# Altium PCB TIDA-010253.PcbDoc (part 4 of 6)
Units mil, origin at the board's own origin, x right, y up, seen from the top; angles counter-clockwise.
Board outline 5525 x 6695 mil, 4 copper layers (Top Layer, Signal Layer 1, Signal Layer 2, Bottom Layer), stack 61.2 mil thick; 522 components, 391 nets, 1722 pads, 1048 vias.
Unrouted connection lines stored in the file: 22.
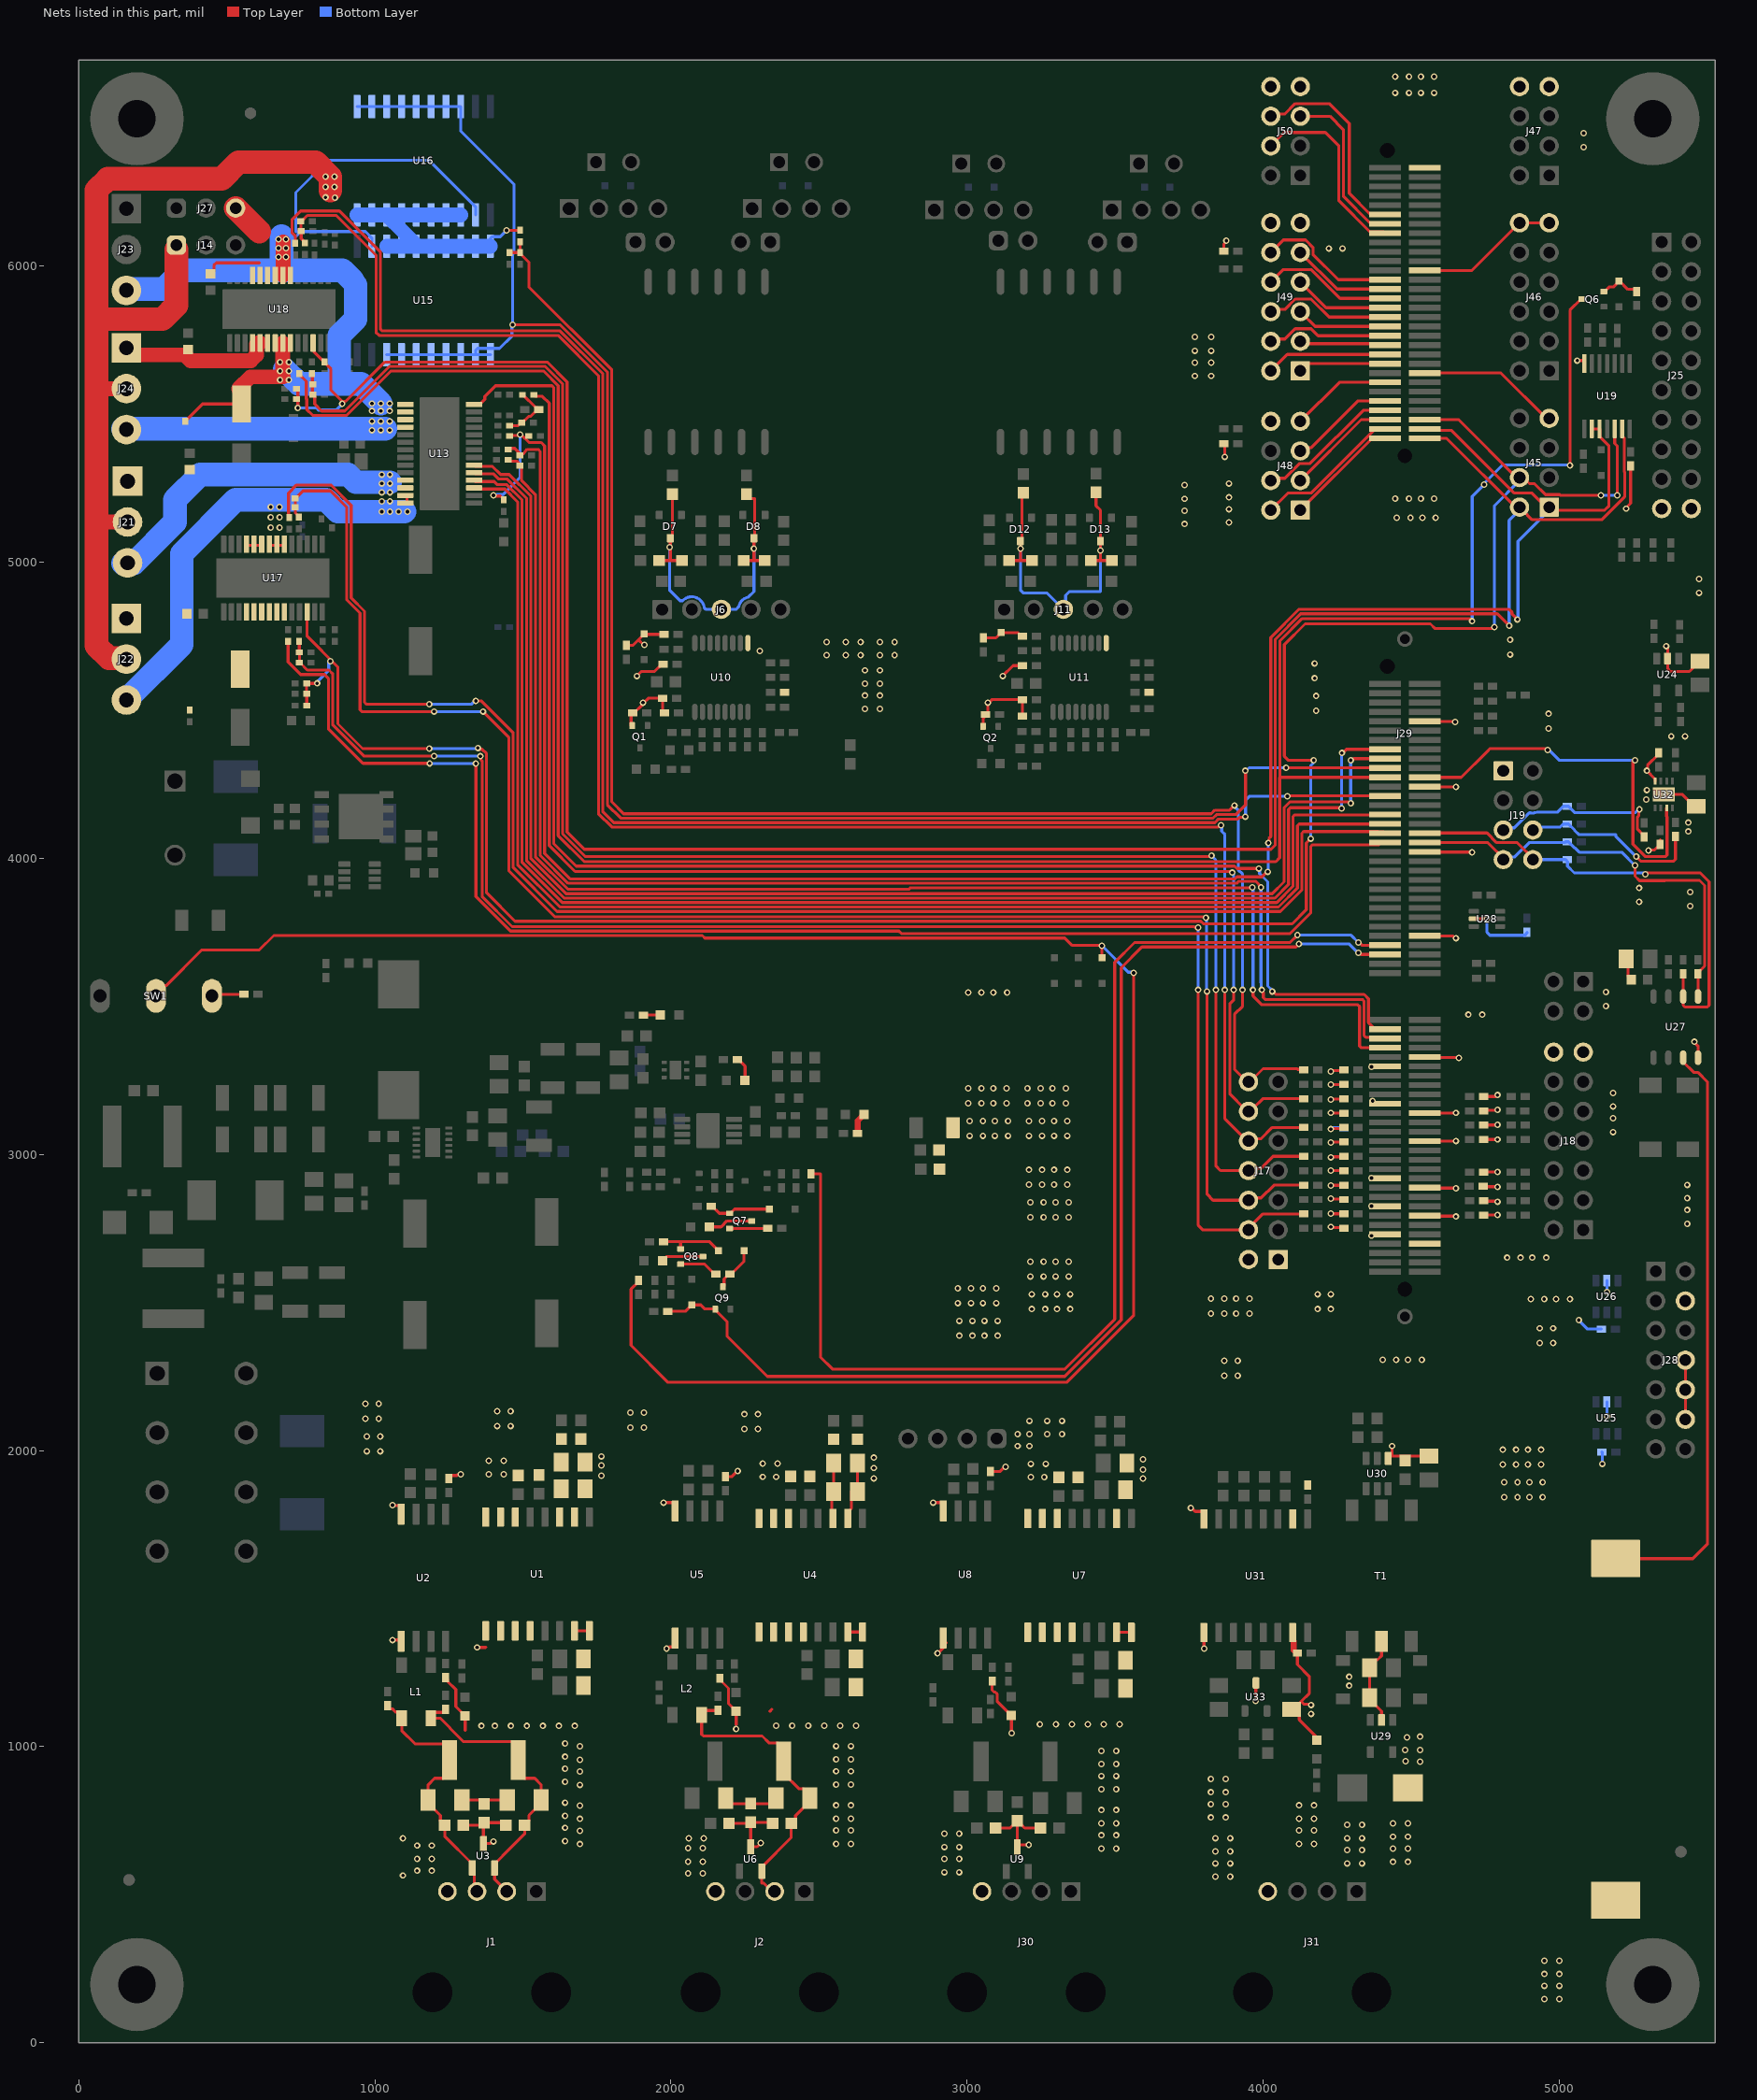
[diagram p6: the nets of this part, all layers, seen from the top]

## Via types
v1: diameter 22, hole 12, Top Layer to Bottom Layer, 944 vias
v2: diameter 19.68, hole 7.87, Top Layer to Bottom Layer, 76 vias
v3: diameter 19.68, hole 7.87, Top Layer to Bottom Layer, tented both sides, 16 vias
v4: diameter 22, hole 12, Top Layer to Bottom Layer, tented both sides, 12 vias

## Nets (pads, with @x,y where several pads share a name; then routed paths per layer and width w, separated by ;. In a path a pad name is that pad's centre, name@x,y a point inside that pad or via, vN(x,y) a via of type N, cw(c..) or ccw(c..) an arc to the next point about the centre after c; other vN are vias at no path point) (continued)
GND: BT1.1 C1.1 C3.2 C8.1 C10.2 C15.1 C17.2 C19.2 C20.2 C21.1 C22.2 C23.2 C24.1 C25.2 C26.2 C27.1 C28.1 C29.2 C30.2 C31.2 C32.1 C33.2 C34.2 C35.1 C36.2 C37.2 C38.1 C39.1 C40.2 C75.2 C107.2 C108.2 C109.2 C110.2 C111.2 C112.2 C113.2 C117.2 C118.2 C119.2 C120.2 C121.2 C122.2 C123.2 C124.2 C125.2 C128.2 C129.2 C131.2 C132.2 C133.2 C134.2 C138.1 C141.2 C142.1 C143.2 C144.2 C145.2 C146.2 C147.2 CO1.2 CO3.2 CO5.2 D7.3 D8.3 D9.2 D12.3 D13.3 D14.2 D23.2 F2.2 J6.3 J11.3 J17.1 J17.2 J18.13 J18.14 J19.1 J25.19 J25.20 J28.4 J28.8 J28.10 J28.12 J29.7 J29.10 J29.13 J29.16 J29.19 J29.22 J29.29 J29.35 J29.38 J29.46 J29.47 J29.65 J29.83 J29.97 J29.111 J29.135 J29.157 J29.179 J45.7 J46.11 J46.12 J47.7 J47.8 J48.8 J49.11 J49.12 J50.7 J50.8 L3.2 L7.2 Q1.2 Q2.2 Q6.2 R6.1 R9.1 R19.1 R21.1 R32.1 R34.1 R46.1 R50.2 R63.1 R67.2 R120.1 R161.1 R201.2 R202.2 R219.2 R220.2 U1.2 U1.6 U1.7 U1.8 U2.4 U4.2 U4.6 U4.7 U4.8 U5.4 U7.2 U7.6 U7.7 U7.8 U8.4 U10.9 U11.9 U19.7 U24.2 U25.2 U26.2 U27.4 U28.2 U30.4 U31.2 U31.8 U32.8 U32.9 | length 9247.4
  Top Layer w10: v1(1060,1815) 1060.71,1814.29 1082.36,1814.29 1089.17,1807.48 U2.4@1089.17,1785.16 ; C1.1@1249.17,1904.65 1249.17,1908.58 1255.98,1915.39 1277.15,1915.39 1281.75,1920 v1@1285,1920 ; C29.2@1850,4718.62 1872.01,4718.62 1889.61,4736.23 ; Q1.2@1864.41,4447.4 1865,4447.99 R50.2@1865,4490 ; R50.2@1871.38,4490 1875.32,4490 1902.7,4517.39 1902.7,4522.7 v1(1905,4525) 1908.25,4525 1923.25,4540 C25.2@1971.38,4540 C23.2@1971.38,4490 ; v1(1885,4615) 1900,4630 1943.82,4630 1968.82,4655 C19.2@1972.76,4655 C19.2@1969.45,4651.69 ; v1(1910,4720) 1906.75,4720 1890.53,4736.23 1889.61,4736.23 ; C20.2@1960,5005 1998.5,5005 ; v1(1975,1824) 2007.36,1824 2014.17,1817.19 U5.4@2014.17,1796.02 ; C22.2@1976.38,4755 1975.53,4755.85 1975.49,4755.81 1910.81,4755.81 D9.2@1910,4756.61 1889.61,4736.23 ; C21.1@2005,5228.5 2005,5089.62 1997.4,5082.03 D7.3@1997.4,5080.06 1997.4,5006.1 1998.5,5005 ; C24.1@2037.01,5005 1998.5,5005 ; C8.1@2184.17,1912.03 2206.17,1912.03 v1(2225,1930.87) ; C28.1@2245,5005 2281,5005 ; C27.1@2255,5228.5 2255,5227.52 2268.7,5213.82 2281.59,5213.82 2282.7,5212.7 2282.7,5082.76 D8.3@2280,5080.06 D8.3@2280,5079.11 ; D8.3@2286.81,5072.3 D8.3@2280,5079.11 ; C26.2@2317.01,5005 2281,5005 ; U4.2@2596.67,1770.75 2596.67,1791.42 2609.17,1803.92 CO3.2@2609.17,1861.89 ; CO3.2@2629.17,1861.89 C10.2@2629.17,1956.89 ; v1(2885,1824) 2912.36,1824 2912.36,1824.29 2919.17,1817.48 U8.4@2919.17,1796.02 ; Q2.2@3054.41,4437.4 3054.41,4473.19 3061.22,4480 R67.2@3061.38,4480 ; C40.2@3055,4747.56 C40.2@3055,4743.62 3097.01,4743.62 D14.2@3115,4761.61 3170.83,4761.61 3182.44,4750 C33.2@3186.38,4750 ; R67.2@3061.38,4485 3063.19,4485 3070,4491.81 v1@3070,4520 ; v1@3075.54,4522.7 3072.7,4522.7 v1@3070,4520 ; C15.1@3079.17,1928.62 3110.37,1928.62 3126.75,1945 v1(3130,1945) ; v1(3120,4615) 3155,4650 C30.2@3186.38,4650 ; C31.2@3141.5,5004.93 3180,5004.93 ; C32.1@3183.57,5240 C32.1@3190.07,5233.5 3185,5228.44 3185,5075.63 D12.3@3180,5070.63 v4(3180,5045) 3180,5004.93 ; C34.2@3186.38,4480 C36.2@3186.38,4535 3083.25,4535 3073.25,4525 v1(3070,4525) v1@3070,4520 ; C35.1@3218.5,5004.93 3180,5004.93 ; C39.1@3417.99,5005 3453.25,5005 ; C38.1@3425.07,5245 C38.1@3435.07,5235 3435.07,5189.93 3450,5175 D13.3@3450,5070.63 D13.3@3450,5069.11 ; D13.3@3456.81,5062.3 D13.3@3450,5069.11 ; C37.2@3488.5,5005 3453.25,5005 ; v1(3755,1805.87) 3758.25,1805.87 3769.82,1794.29 3792.36,1794.29 3799.17,1787.48 U31.8@3799.17,1768.82 ; R202.2@3866.38,5400 3870,5396.38 v4(3870,5355) ; R201.2@3866.38,6050 3866.38,6073.6 3875,6082.22 v4(3875,6085) ; J48.8@4025,5475 J48.8@4032.56,5482.56 ; v1@4230,2755 4232.3,2752.7 4268.67,2752.7 C109.2@4271.38,2750 ; v1@4230,2800 4230.68,2799.32 4270.7,2799.32 C110.2@4271.38,2798.64 ; v1@4230,2850 4231.36,2848.64 4270.01,2848.64 C118.2@4271.38,2847.27 ; v1@4230,2895 4230.45,2895.45 4270.92,2895.45 C119.2@4271.38,2895.91 ; v1@4230,2945 4230.23,2944.77 4271.15,2944.77 C122.2@4271.38,2944.55 ; v1@4230,2990 4231.59,2991.59 4269.79,2991.59 C123.2@4271.38,2993.18 ; v1@4230,3040 4230.91,3040.91 4270.47,3040.91 C124.2@4271.38,3041.82 ; v1@4230,3140 4230.45,3139.55 4272.3,3139.55 C133.2@4272.76,3139.09 ; v1@4230,3185 4231.36,3186.36 4270.01,3186.36 C134.2@4271.38,3187.73 ; v1@4230,3235 4230.68,3235.68 4270.7,3235.68 C146.2@4271.38,3236.36 ; v1@4230,3280 4232.3,3282.3 4268.67,3282.3 C147.2@4271.38,3285 ; v1@4232.3,3087.3 4268.22,3087.3 C125.2@4271.38,3090.45 ; J29.46@4360,3295 4360.83,3295.83 4410.31,3295.83 J29.46@4411.14,3296.65 ; v1(4365,2725) 4367.3,2727.3 4408.71,2727.3 J29.10@4411.14,2729.72 ; v1(4365,2825) 4365.39,2824.61 4410.75,2824.61 J29.16@4411.14,2824.21 ; J29.22@4370,2920 4370.65,2919.35 4410.49,2919.35 J29.22@4411.14,2918.7 ; J29.38@4370,3180 4373.25,3180 4377.74,3175.51 4406.3,3175.51 J29.38@4411.14,3170.67 ; v1(4435,2015) 4435,1980.87 C141.2@4559.17,1980.87 ; J29.13@4545,2792.72 4546.36,2791.36 4648.64,2791.36 v1(4650,2790) ; J29.19@4545,2887.2 4546.1,2886.1 4648.9,2886.1 v1(4650,2885) ; J29.29@4545,3044.69 4545.16,3044.84 4649.84,3044.84 v1(4650,3045) ; J29.35@4545,3139.17 4545.41,3139.59 4649.59,3139.59 v1(4650,3140) ; J29.47@4545,3328.15 4546.57,3326.57 4658.43,3326.57 v1(4660,3325) ; J29.65@4545,3737.6 4639.15,3737.6 4646.75,3730 v1(4650,3730) ; J29.83@4545,4021.06 4545.53,4020.53 4704.47,4020.53 v1(4705,4020) ; J29.97@4545,4241.54 4545.77,4240.77 4649.23,4240.77 v1(4650,4240) ; J29.111@4545,4462.01 4546,4461 4644,4461 v1@4645,4460 ; J29.135@4545,5637.91 4802.09,5637.91 J45.7@4957.44,5482.56 ; J29.157@4545,5984.37 4704.37,5984.37 J46.12@4865,6145 J46.11@4965,6145 ; U28.2@4710.71,3795 v1(4755,3795) ; C120.2@4742.24,2891.67 4743.08,2890.83 4792.67,2890.83 v1@4793.5,2890 ; C111.2@4743.62,2795 v1@4793.5,2795 ; C112.2@4743.62,2843.33 4745.29,2841.67 4791.83,2841.67 v1@4793.5,2840 ; C121.2@4743.62,2940 v1@4793.5,2940 ; C131.2@4743.62,3050 v1@4793.5,3050 ; C132.2@4743.62,3098.33 4744.46,3099.17 4792.67,3099.17 v1@4793.5,3100 ; C144.2@4743.62,3146.67 4745.29,3148.33 4791.83,3148.33 v1@4793.5,3150 ; C145.2@4743.62,3195 4785.25,3195 4790.25,3200 v1@4793.5,3200 ; v1(5060,5680) 5081.93,5680 5083.82,5678.11 U19.7@5083.82,5670 ; Q6.2@5149.9,5913.09 5152.46,5913.09 5167.53,5928.16 5181.55,5928.16 5202.5,5949.11 5231.12,5920.49 5250.69,5920.49 5257.5,5913.68 R120.1@5257.5,5909.74 ; C143.2@5212.5,3659.49 5231.63,3640.36 5231.63,3600.24 C108.2@5242.38,3589.49 ; v1(5225,5180) 5225,5183.25 5240,5198.25 C75.2@5240,5325 ; v1(5300,4026) 5301.3,4027.3 5320.92,4027.3 5329.25,4035.63 5333.19,4035.63 R219.2@5339.31,4041.75 ; U32.8@5322.32,4260 5322.32,4266.73 5321.38,4267.68 5321.38,4268.62 v1(5295,4295) 5297.3,4297.3 5297.3,4313.36 5335,4351.06 R220.2@5335,4355 ; U32.9@5338.07,4214.72 U32.9@5351.85,4214.72 5415.15,4214.72 5454.88,4175 C142.1@5461.38,4175 ; R219.2@5340,4046.38 5340,4042.44 R219.2@5339.31,4041.75 ; R219.2@5340,4061.38 5339.31,4060.69 R219.2@5339.31,4041.75 ; v1@5353.98,4715.87 5353.98,4715.49 v1@5356.79,4712.68 ; v1(5360,4715.87) 5359.98,4712.62 5365,4707.6 U24.2@5365,4674.13 5365,4640 5375,4630 5438.5,4630 5473.5,4665 C107.2@5490,4665 ; J28.12@5425,2105 J28.10@5425,2205 J28.8@5425,2305 ; v1(5455,3380) 5455,3378.25 5467.5,3365.75 U27.4@5467.5,3326.14 U27.4@5467.5,3314.93 ; D8.3@2280,5079.11 v4(2280,5045) 2280,5006 2281,5005 ; D13.3@3450,5069.11 v4(3450,5038.68) 3450,5008.25 3453.25,5005
  Bottom Layer w10: v4(1995,5050) 1995,4905 2030.88,4869.12 2035.02,4869.12 2039.07,4869.12 cw(c2070,4840) 2111.71,4848.04 ccw(c2121.52,4850) 2115.74,4841.84 2118.34,4840 2121.52,4840 J6.3@2170,4840 2220,4840 2228.35,4848.35 cw(c2270,4840) 2261.65,4881.65 2280,4900 v4(2280,5045) ; v4(3180,5045) 3180,4905 3190,4895 3270,4895 J11.3@3325,4840 3332.48,4847.48 3332.48,4887.48 3345,4900 3450,4900 v4(3450,5038.68) ; v1(4227.5,3085) 4230.75,3085 4235.75,3090 R161.1@4271.38,3090 ; v1(4755,3795) 4755,3749.36 4765.11,3739.25 4883.19,3739.25 4883.19,3740 4890,3746.81 C117.2@4890,3750 ; v1(5065,2440) 5095,2410 C129.2@5141.38,2410 ; C128.2@5142.76,1995 5145,1992.76 v1(5145,1955) ; v1(5160,2115) U25.2@5160,2164.13 ; v1(5160,2535) U26.2@5160,2574.13
  other v1: 4949.31,147.36 4999.31,147.36 4949.31,192.36 4999.31,192.36 4949.31,232.36 4999.31,232.36 4949.31,277.36 4999.31,277.36 4813.14,1842.59 4858.14,1842.59 4898.14,1842.59 4943.14,1842.59 4813.14,1892.59 4858.14,1892.59 4898.14,1892.59 4943.14,1892.59 3594,1905 2685,1905.87 3215,1910 3260,1910 2310,1910.87 2355,1910.87 1765,1915 1290,1920 1385,1920 1435,1920 3594,1935 2685,1940.87 1765,1950 4808.14,1952.59 4853.14,1952.59 4893.14,1952.59 4938.14,1952.59 3215,1955 3265,1955 2310,1955.87 2360,1955.87 1385,1965 1435,1965 3594,1970 2685,1975.87 1765,1980 973.14,1997.59 1018.14,1997.59 4808.14,2002.59 4853.14,2002.59 4893.14,2002.59 4938.14,2002.59 3170,2015 3210,2015 973.14,2047.59 1018.14,2047.59 3170,2055 3210,2055 3270,2055 3320,2055 2248.14,2072.59 2293.14,2072.59 1863.14,2077.59 1908.14,2077.59 1413.14,2082.59 1458.14,2082.59 3210,2100 3270,2100 3320,2100 968.14,2107.59 1013.14,2107.59 2248.14,2122.59 2293.14,2122.59 1863.14,2127.59 1908.14,2127.59 1413.14,2132.59 1458.14,2132.59 968.14,2157.59 1013.14,2157.59 3868.14,2252.59 3913.14,2252.59 3868.14,2302.59 3913.14,2302.59 4403.14,2306 4448.14,2306 4488.14,2306 4535,2306 4933.14,2362.59 4978.14,2362.59 2973.14,2387.59 3018.14,2387.59 3058.14,2387.59 3103.14,2387.59 4933.14,2412.59 4978.14,2412.59 2973.14,2437.59 3018.14,2437.59 3058.14,2437.59 3103.14,2437.59 3823.14,2462.59 3868.14,2462.59 3908.14,2462.59 3953.14,2462.59 3218.14,2477.59 3263.14,2477.59 3303.14,2477.59 3348.14,2477.59 4183.14,2477.59 4228.14,2477.59 2968.14,2497.59 3013.14,2497.59 3053.14,2497.59 3098.14,2497.59 4903.14,2511 4948.14,2511 4988.14,2511 5035,2511 3823.14,2512.59 3868.14,2512.59 3908.14,2512.59 3953.14,2512.59 3218.14,2527.59 3263.14,2527.59 3303.14,2527.59 3348.14,2527.59 4183.14,2527.59 4228.14,2527.59 2968.14,2547.59 3013.14,2547.59 3053.14,2547.59 3098.14,2547.59 3213.14,2587.59 3258.14,2587.59 3298.14,2587.59 3343.14,2587.59 3213.14,2637.59 3258.14,2637.59 3298.14,2637.59 3343.14,2637.59 4823.14,2651 4868.14,2651 4908.14,2651 4955,2651 4227.5,2755 5431,2765 3213.14,2787.59 3258.14,2787.59 3298.14,2787.59 3343.14,2787.59 4790.5,2795 4227.5,2800 5431,2811.86 3213.14,2837.59 3258.14,2837.59 3298.14,2837.59 3343.14,2837.59 4790.5,2840 4227.5,2850 5431,2851.86 4790.5,2890 4227.5,2895 5431,2896.86 3208.14,2897.59 3253.14,2897.59 3293.14,2897.59 3338.14,2897.59 4365,2920 4790.5,2940 4227.5,2945 3208.14,2947.59 3253.14,2947.59 3293.14,2947.59 3338.14,2947.59 4227.5,2990 4227.5,3040 4790.5,3050 3008.14,3062.59 3053.14,3062.59 3093.14,3062.59 3138.14,3062.59 3208.14,3062.59 3253.14,3062.59 3293.14,3062.59 3338.14,3062.59 5181,3075 4790.5,3100 3008.14,3112.59 3053.14,3112.59 3093.14,3112.59 3138.14,3112.59 3208.14,3112.59 3253.14,3112.59 3293.14,3112.59 3338.14,3112.59 5181,3121.86 4227.5,3140 4790.5,3150 5181,3161.86 3003.14,3172.59 3048.14,3172.59 3088.14,3172.59 3133.14,3172.59 3203.14,3172.59 3248.14,3172.59 3288.14,3172.59 3333.14,3172.59 4369,3180 4227.5,3185 4790.5,3200 5181,3206.86 3003.14,3222.59 3048.14,3222.59 3088.14,3222.59 3133.14,3222.59 3203.14,3222.59 3248.14,3222.59 3288.14,3222.59 3333.14,3222.59 4227.5,3235 4227.5,3280 4365,3295 4692.26,3471.4 4739.12,3471.4 5156.4,3500.88 3003.14,3546 3048.14,3546 3088.14,3546 3135,3546 5156.4,3547.74 5441.4,3838.46 5268.6,3852.26 5441.4,3885.31 5268.6,3899.12 5435,4090 5435,4120 5292.5,4197.5 5295,4230 5377.26,4411.4 5424.12,4411.4 4963.14,4437.59 4648,4460 4963.14,4487.59 4178.14,4497.59 2655.21,4504.08 2705.21,4504.08 4178.14,4547.59 2655.21,4549.08 2705.21,4549.08 2655.21,4589.08 2705.21,4589.08 4173.14,4607.59 2655.21,4634.08 2705.21,4634.08 4173.14,4657.59 2525,4685 2590,4685 2640,4685 2705,4685 2755,4685 4833.14,4687.59 2300,4700 2525,4730 2590,4730 2640,4730 2705,4730 2755,4730 4833.14,4737.59 5471.4,4895.88 5471.4,4942.74 3734,5128.14 3884,5133.14 4450,5149 4496.86,5149 4536.86,5149 4581.86,5149 3734,5173.14 3884,5178.14 3734,5213.14 4445,5214 4491.86,5214 4531.86,5214 4576.86,5214 3884,5218.14 3734,5260 3884,5265 3769,5628.14 3824,5628.14 3769,5673.14 3824,5673.14 3769,5713.14 3824,5713.14 3769,5760 3824,5760 4220.88,6058.6 4267.74,6058.6 5081.4,6400.88 5081.4,6447.74 4445,6584 4491.86,6584 4531.86,6584 4576.86,6584 4445,6639 4491.86,6639 4531.86,6639 4576.86,6639
GND0: C2.1 C4.2 C5.2 C6.1 C7.1 CO2.2 D1.1 J1.4 U1.9 U1.10 U1.11 U1.12 U1.15 U1.16 U2.5 U3.3 | length 570.4
  Top Layer w10: v1(1060,1360) 1085.19,1360 U2.5@1089.17,1356.02 ; C2.1@1239.17,1232.76 1245.98,1225.94 1245.98,1220.27 1273.42,1192.83 1273.42,1135.28 1305,1103.7 1305,1055.29 ; C7.1@1299.17,735 1360.66,735 C6.1@1366.77,741.1 ; v1(1345,1335) 1373.14,1335 1374.17,1336.02 ; v1(1400,680) 1396.75,680 1389.43,672.68 U3.3@1366.77,672.68 C6.1@1366.77,741.1 ; C5.2@1442.67,735 1434.17,743.5 C6.1@1369.17,743.5 C6.1@1366.77,741.1 ; U1.15@1674.17,1391.02 U1.16@1724.17,1391.02
  other v1: 1095,565 1142.59,580.99 1192.59,580.99 1142.59,620.99 1192.59,620.99 1142.59,665.99 1192.59,665.99 1692.59,670.99 1642.59,680.99 1095,690 1692.59,715.99 1642.59,725.99 1692.59,755.99 1642.59,765.99 1692.59,800.99 1642.59,810.99 1692.59,870.99 1642.59,880.99 1692.59,915.99 1642.59,925.99 1692.59,955.99 1642.59,965.99 1692.59,1000.99 1642.59,1010.99 1360,1070 1405.47,1070 1459.38,1070 1513.28,1070 1567.19,1070 1621.09,1070 1675,1070
GND1: C9.1 C11.2 C12.2 C13.1 C14.1 CO4.2 D2.1 J2.4 U4.9 U4.10 U4.11 U4.12 U4.15 U4.16 U5.5 U6.3 | length 569.1
  Top Layer w10: v1(1985,1330.87) 1988.25,1330.87 1993.84,1336.46 2007.36,1336.46 2014.17,1343.27 U5.5@2014.17,1366.89 U5.5@2013.14,1365.87 ; C9.1@2164.17,1230.87 2164.17,1226.93 2194.25,1196.85 2194.25,1145.12 D2.1@2220,1119.37 2220,1074.11 ; C14.1@2195.66,740.87 2265.66,740.87 C13.1@2269.17,744.37 ; v1(2302.77,674.3) 2290.68,662.2 U6.3@2269.17,662.2 C13.1@2269.17,744.37 ; 2333.5,1119.37 2340,1125.87 ; C12.2@2342.67,740.87 2339.17,744.37 C13.1@2269.17,744.37 ; U4.15@2596.67,1386.89 U4.16@2646.67,1386.89
  other v1: 2057.59,571.86 2107.59,571.86 2057.59,611.86 2107.59,611.86 2057.59,656.86 2107.59,656.86 2557.59,671.86 2607.59,671.86 2060,690 2110,690 2557.59,716.86 2607.59,716.86 2557.59,756.86 2607.59,756.86 2557.59,801.86 2607.59,801.86 2557.59,871.86 2607.59,871.86 2557.59,916.86 2607.59,916.86 2557.59,956.86 2607.59,956.86 2557.59,1001.86 2607.59,1001.86 2220,1060 2355.47,1070.87 2409.38,1070.87 2463.28,1070.87 2517.19,1070.87 2571.09,1070.87 2625,1070.87
GND2: C114.2 C139.1 C140.2 CO12.2 D5.1 J31.4 R210.1 T1.5 U29.2 U31.9 U31.15 U33.3 | length 849.4
  Top Layer w10: U31.9@3799.17,1384.96 3799.58,1384.54 3799.58,1331.28 v1(3800,1330.87) ; v1(3974.17,1154.76) 3974.58,1155.18 3974.58,1208.68 U33.3@3975,1209.09 ; R210.1@4095,1125.87 R210.1@4101.5,1125.87 ; C139.1@4115,1315.87 4115,1277.46 4155,1237.46 4155,1179.37 4128.25,1152.62 ; v1(4161.01,1140.76) 4158.71,1143.05 4137.81,1143.05 4128.25,1152.62 ; D5.1@4180,1032.36 4121.5,1090.86 4121.5,1105.87 R210.1@4101.5,1125.87 ; U29.2@4399.17,1097.87 U29.2@4399.17,1090 4398.93,1090.24 4398.93,1119.6 4359.17,1159.37 C140.2@4359.17,1165.87 CO12.2@4359.17,1266.81 4359.17,1273.31 4379.17,1293.31 4385.67,1293.31 4399.17,1306.82 T1.5@4399.17,1355.63 ; R210.1@4101.5,1125.87 4128.25,1152.62
  Top Layer w20: C139.1@4102.36,1325.24 U31.15@4102.36,1356.1
  other v1: 3837.91,560.98 3887.91,560.98 3837.91,605.98 3887.91,605.98 4282.91,605.98 4332.91,605.98 4437.91,610.98 4487.91,610.98 3837.91,645.98 3887.91,645.98 4282.91,650.98 4332.91,650.98 4437.91,655.98 4487.91,655.98 4120.83,671.95 4170.83,671.95 3837.91,690.98 3887.91,690.98 4282.91,690.98 4332.91,690.98 4437.91,695.98 4487.91,695.98 4120.83,716.95 4170.83,716.95 4282.91,735.98 4332.91,735.98 4437.91,740.98 4487.91,740.98 4120.83,756.95 4170.83,756.95 3822.91,760.98 3872.91,760.98 4120.83,801.95 4170.83,801.95 3822.91,805.98 3872.91,805.98 3822.91,845.98 3872.91,845.98 3822.91,890.98 3872.91,890.98 4528.76,948.86 4480,950.87 4478.76,988.86 4528.76,988.86 4485,1030.87 4528.76,1033.86 4161.01,1110.76 4290,1205.87 4290,1235.87
GND4: C16.1 C18.2 C135.2 C136.1 C137.1 CO11.2 D3.1 J30.4 U7.9 U7.10 U7.11 U7.12 U7.15 U7.16 U8.5 U9.3 | length 601.2
  Top Layer w10: v1(2900,1315) 2925,1340 2918.14,1340 U8.5@2919.17,1341.02 ; U8.5@2928.14,1350 U8.5@2929.17,1351.02 ; C16.1@3084.17,1221.38 3084.17,1190.63 3090.43,1184.37 3095.12,1184.37 3100.98,1178.51 3100.98,1153.19 D3.1@3149.17,1105 v1@3149.17,1054.08 ; C137.1@3095.66,725 3145.15,725 C136.1@3169.17,749.02 ; U9.3@3169.17,654.24 U9.3@3169.17,661.34 U9.3@3169.17,661.62 ; C136.1@3169.17,750 C136.1@3169.17,749.02 ; v1(3207.77,668.43) 3175.98,668.43 U9.3@3169.17,661.62 ; C135.2@3247.67,725 3194.17,725 3183.85,735.31 3182.87,735.31 C136.1@3169.17,749.02 ; U7.15@3504.17,1386.14 U7.16@3554.17,1386.14 ; U9.3@3169.17,661.62 C136.1@3169.17,749.02
  other v1: 2922.91,575.98 2972.91,575.98 2922.91,620.98 2972.91,620.98 3452.91,655.98 3502.91,655.98 2922.91,660.98 2972.91,660.98 3452.91,700.98 3502.91,700.98 2922.91,705.98 2972.91,705.98 3452.91,740.98 3502.91,740.98 3452.91,785.98 3502.91,785.98 3452.91,855.98 3502.91,855.98 3452.91,900.98 3502.91,900.98 3452.91,940.98 3502.91,940.98 3452.91,985.98 3502.91,985.98 3150,1045 3245.47,1075 3299.38,1075 3353.28,1075 3407.19,1075 3461.09,1075 3515,1075
HDC_Alert: J29.99 U32.3 | length 1324.9
  Top Layer w10: J29.99@4545,4273.03 4668.03,4273.03 4755,4360 4765,4370 4951.75,4370 4956.75,4365 v1(4960,4365) ; v1@5248,4330 5248,4047 5290,4005 5357.33,4005 5363.19,4010.86 5363.19,4139.89 5361.69,4141.39 U32.3@5361.69,4169.45
  Bottom Layer w10: 4970,4360 5000,4330 v1@5248,4330
  other v1: 5255,4330
HS_CS: J17.12 R80.1 R198.2 | length 4938.3
  Top Layer w10: R80.1@1537.64,5563.98 1542.48,5559.13 1565.87,5559.13 1589,5536 1589,4042.36 1676.36,3955 3887.75,3955 3891.75,3951 v1(3895,3951) ; v1(3900,3555) 3900,3521.79 3887.52,3509.31 3887.52,3202.48 3935,3155 3965,3155 3997.73,3187.73 R198.2@4136.38,3187.73
  Bottom Layer w10: v1(3895,3951) 3900,3946 v1(3900,3555)
HS_CS_L: R79.1 R80.2 R81.2 R233.2 | length 193.7
  Top Layer w10: R233.2@1458.33,5460 1483.66,5460 1493.66,5470 1497.6,5470 1519.11,5491.52 1526.2,5491.52 1549.68,5515 R81.2@1553.62,5515 1546.81,5521.81 1542.4,5521.81 1500.24,5563.98 R80.2@1498.27,5563.98
HS_DIAG: J29.54 U13.14 | length 5174.1
  Top Layer w10: U13.14@1341.1,5532.36 1354.29,5532.36 1371.39,5549.46 1371.39,5558.95 1407.44,5595 1598.14,5595 1604,5589.14 1604,4048.57 1679.57,3973 3902.7,3973 3910.7,3965 v1(3985,3965) ; v1@4026.76,3544 v1@4030,3544 ; v1@4032.3,3547.7 v1(4030,3550) 4031.86,3550 4041.86,3540 4340.36,3540 4355,3525.36 4355,3445 4372.52,3427.48 4406.3,3427.48 J29.54@4411.14,3422.64
  Bottom Layer w10: v1(3985,3965) 3987.3,3962.7 3987.3,3947.7 4015,3920 4015,3568.25 4030,3553.25 v1(4030,3550)
HS_EN1: J29.90 U13.3 | length 4612.9
  Top Layer w10: U13.3@1339.96,5246.02 1439.12,5246.02 1482.07,5203.08 1482.07,4915.43 1482.07,3977.93 1625,3835 4051.21,3835 4115,3898.79 4115,4109.42 4120.86,4115.28 4410.87,4115.28 J29.90@4411.14,4115.55
HS_EN2: J29.92 U13.4 | length 4637.5
  Top Layer w10: U13.4@1339.96,5271.61 1403.39,5271.61 1413.98,5261.02 1445.34,5261.02 1497.07,5209.29 1497.07,3985.8 1632.87,3850 4045,3850 4100,3905 4100,4140.17 4105.86,4146.02 4410.12,4146.02 J29.92@4411.14,4147.05
HS_EN3: J29.106 U13.5 | length 4855.7
  Top Layer w10: U13.5@1339.96,5297.2 1401.42,5297.2 1418.62,5280 1447.57,5280 1512.07,5215.5 1512.07,3992.01 1639.08,3865 4038.79,3865 4085,3911.21 4085,4164.14 4090.86,4170 4261.75,4170 v1(4264.25,4167.5) 4266.75,4165 v1@4270,4165 ; v1(4265,4355) 4268.25,4355 4280.77,4367.52 J29.106@4411.14,4367.52
  Bottom Layer w10: v1(4264.25,4167.5) 4264.63,4167.87 4264.63,4354.63 v1(4265,4355)
HS_EN4: J29.104 U13.6 | length 4810.1
  Top Layer w10: U13.6@1339.96,5322.8 1397.04,5322.8 1424.83,5295 1453.79,5295 1527.07,5221.72 1527.07,3998.22 1645.29,3880 4030,3880 4070,3920 4070,4170.36 4089.64,4190 4286.75,4190 4291.75,4185 v1(4295,4185) ; v1(4295,4330) 4298.25,4330 4304.27,4336.02 J29.104@4411.14,4336.02
  Bottom Layer w10: v1(4295,4185) v1(4295,4330)
HS_OUT1: C60.1 C62.2 J22.3 U13.27 U13.28 U17.6 U17.7 U17.8 U17.21 U17.22 U17.23 | length 1628.8
  Top Layer w10: C60.1@518.5,4695 545,4668.5 C60.1@545,4638.43 545,4606.93 C60.1@571.5,4580.43 ; U17.8@643.23,5056.5 U17.6@694.41,5056.5 ; U13.28@1108.82,5199.69 U13.27@1108.82,5225.28
  Bottom Layer w80: J22.3@161,4533.87 347.91,4720.78 347.91,5027.91 530,5210 678.23,5210 835,5210 875,5170 v1(1023.03,5170) v1(1051,5170) v1(1080,5170) v1@1100,5170
  other v1: 648.5,5115.91 678.5,5115.91 648.5,5150.91 678.5,5150.91 1110,5170 678.23,5185.12 648.5,5185.91 1023.03,5204.02 1051,5205
HS_OUT2: J21.3 U13.25 U13.26 | length 1080.4
  Bottom Layer w80: J21.3@150,4995 185.81,4995 325,5134.19 325,5210 410,5295 910,5295 935.98,5269.02 1023.03,5269.02 v1@1051,5269.02
  other v1: 1023.03,5235 1051,5235 1023.03,5265.02 1051,5265.02 1023.03,5295 1051,5295
HS_OUT3: J24.3 U13.17 U13.18 | length 885
  Bottom Layer w80: J24.3@150,5450 161,5450 996,5450 1035,5450
  other v1: 990,5445 1020,5445 1050,5445 990,5475 1020,5475 1050,5475
HS_OUT4: C61.1 C63.2 J23.3 U13.15 U13.16 U15.12 U16.12 U18.6 U18.7 U18.8 U18.21 U18.22 U18.23 | length 3584.3
  Top Layer w10: C63.2@360,5475 360,5476.97 364.84,5481.81 366.81,5481.81 418.43,5533.43 C61.1@550,5533.43 550,5558.5 C61.1@523.5,5585 ; U13.15@1108.82,5532.36 1117.28,5532.36 U13.15@1121.14,5536.22
  Top Layer w50: C61.1@540,5585 579.91,5624.91 604.19,5624.91 604.28,5625 689.22,5625 ; U18.22@689.22,5739.43 689.22,5625 ; U18.7@689.22,5967.78 690,5968.56 690,6080 ; 690,5625 689.22,5625
  Bottom Layer w10: v1@694.73,6059.73 750.51,6115.51 ; U15.12@990,6066.14 990,6093.7 968.19,6115.51 750.51,6115.51 ; U16.12@1340,6171.93 1340,6199.49 1183.63,6355.86 841.72,6355.86 733.1,6247.24 733.1,6115.51 750.51,6115.51
  Bottom Layer w80: J23.3@161,5917.2 164.83,5921.03 286.03,5921.03 350,5985 890,5985 925,5950 ; 685,5985 685,6100 ; 695,5650 743.6,5601.4 880,5601.4 ; 935,5935 935,5820 880,5765 880,5601.4 ; v1(1020,5535) 953.6,5601.4 880,5601.4
  other v1: 990,5510 1020,5510 1050,5510 990,5535 1050,5535 680,5615 710,5615 680,5645 710,5645 680,5675 710,5675 675,6030 700,6030 675,6060 700,6060 675,6090 700,6090
HSD_FAULT1: J29.123 J45.1 R78.1 R87.2 R232.2 U19.9 U19.10 | length 7423.5
  Top Layer w10: v1(1400,5225) 1402.3,5222.7 1423.95,5222.7 1435,5211.65 R87.2@1435,5209.69 ; R232.2@1455,5426.67 1497.6,5426.67 1521.09,5403.18 1561.82,5403.18 1573.19,5391.81 1573.19,4015.74 1658.93,3930 3903.7,3930 3910.7,3937 3995.23,3937 4012.23,3954 v1(4015,3954) ; v1(4017.08,4050.75) 4019.38,4053.04 4019.38,4067.39 4025,4073.01 4025,4745 4120,4840 4830,4840 4839.12,4830.88 4839.12,4824.96 v1(4858.09,4806) ; J29.123@4545,5448.94 4549.84,5444.09 4635.83,5444.09 4847.4,5232.52 4907.48,5232.52 4965,5175 5152.25,5175 5166.81,5189.56 5166.81,5391.95 5136.89,5421.87 5136.89,5447.64 U19.10@5135,5449.53 U19.9@5109.41,5449.53
  Bottom Layer w10: 1412.3,5227.3 1432.3,5227.3 1490,5285 v1(1490,5430) ; v1(4015,3954) 4016.04,3955.04 4016.04,4049.7 v1(4017.08,4050.75) ; v1(4858.09,4806) 4860,4807.91 4860,5070 J45.1@4965,5175
HSD_SEH: J29.50 R76.1 R230.2 | length 4821.8
  Top Layer w10: R230.2@1455,5340 1480.63,5340 1488.5,5332.13 1488.5,5329.84 1493.35,5325 1495.63,5325 1495.63,5274.37 1542.07,5227.93 1542.07,4004.44 1651.51,3895 2803.63,3895 2808.63,3900 3964,3900 v1@3965,3901 ; v1(3965,3555) 3965,3535 3995,3505 4319.14,3505 4325,3499.14 4325,3365.5 4330.86,3359.65 J29.50@4411.14,3359.65
  Bottom Layer w10: v1(3965,3555) v1@3965,3901
  other v1: 3963,3901
HSD_SEL: J29.52 R77.1 R231.2 | length 4888.7
  Top Layer w10: R231.2@1454.37,5383.33 1471.98,5383.33 1495.32,5360 1495.32,5363.03 1497.13,5364.84 1500.16,5364.84 1507.87,5372.56 1507.87,5373.98 1513.73,5379.84 1551.56,5379.84 1558.19,5373.22 1558.19,4009.53 1652.72,3915 3909.91,3915 3916.91,3922 3973.7,3922 3992,3903.7 v1(3992,3901) ; v1(3995,3555) 3995,3551.75 4000,3546.75 4000,3528.86 4005.86,3523 4334.14,3523 4340,3517.14 4340,3400.86 4345.86,3395 4407.28,3395 J29.52@4411.14,3391.14
  Bottom Layer w10: v1(3992,3901) 3991.9,3900.9 3991.9,3580 3992.7,3579.2 3992.7,3557.3 v1(3995,3555)
"HSEC_GPMC0_AD1 (11)": J29.154 J49.9 | length 337.3
  Top Layer w10: J49.9@4125,6045 4248.62,5921.38 J29.154@4411.14,5921.38
"HSEC_GPMC0_AD3 (11)": J29.156 J49.10 | length 473.6
  Top Layer w10: J49.10@4025,6045 4067.48,6087.48 4142.6,6087.48 4167.48,6062.6 4167.48,6038.57 4253.18,5952.87 J29.156@4411.14,5952.87
"HSEC_GPMC0_AD11 (9)": J29.166 J50.4 | length 653.3
  Top Layer w10: J50.4@4025,6405 4070,6450 4209.14,6450 4255,6404.14 4255,6220 4360,6115 4406.5,6115 J29.166@4411.14,6110.35
"HSEC_GPMC0_AD13 (9)": J29.168 J50.5 | length 568.4
  Top Layer w10: J50.5@4125,6505 4225,6505 4270,6460 4270,6235 4360,6145 4407.99,6145 J29.168@4411.14,6141.85
"HSEC_GPMC0_AD15 (9)": J29.170 J50.6 | length 696.4
  Top Layer w10: J50.6@4025,6505 4032.56,6512.56 4072.48,6512.56 4107.4,6547.48 4222.52,6547.48 4290,6480 4290,6245 4361.65,6173.35 J29.170@4411.14,6173.35
"HSEC_MII0_RXD1 (13)": J29.126 J48.3 | length 371.2
  Top Layer w10: J48.3@4125,5275 4330.43,5480.43 J29.126@4411.14,5480.43
"HSEC_MII0_RXD3 (13)": J29.128 J48.4 | length 484.3
  Top Layer w10: J48.4@4025,5275 4032.56,5282.56 4072.48,5282.56 4122.44,5332.52 4157.67,5332.52 4337.08,5511.93 J29.128@4411.14,5511.93
"HSEC_MII0_RXDV (13)": J29.124 J48.2 | length 499.6
  Top Layer w10: J48.2@4025,5175 4082.52,5232.52 4160.95,5232.52 4372.52,5444.09 4392.52,5444.09 4397.36,5448.94 J29.124@4411.14,5448.94
"HSEC_MII0_RXLINK (13)": J29.122 J48.1 | length 386.6
  Top Layer w10: J48.1@4125,5175 4367.44,5417.44 J29.122@4411.14,5417.44
"HSEC_MII0_TXD3 (13)": J29.134 J48.7 | length 340.6
  Top Layer w10: J48.7@4125,5475 4256.42,5606.42 J29.134@4411.14,5606.42
"HSEC_MII0_TXEN (13)": J29.130 J48.5 | length 355.9
  Top Layer w10: J48.5@4125,5375 4135.52,5385.52 4160.52,5385.52 4318.43,5543.43 J29.130@4411.14,5543.43
"HSEC_MII1_COL (14)": J29.138 J49.1 | length 296.3
  Top Layer w10: J49.1@4125,5645 4149.41,5669.41 J29.138@4411.14,5669.41
"HSEC_MII1_RXD1 (14)": J29.144 J49.4 | length 413.5
  Top Layer w10: J49.4@4025,5745 4032.56,5752.56 4072.48,5752.56 4107.4,5787.48 4161.31,5787.48 4184.89,5763.9 J29.144@4411.14,5763.9
"HSEC_MII1_RXD3 (14)": J29.146 J49.5 | length 309.6
  Top Layer w10: J49.5@4125,5845 4130,5845 4130,5840 4174.61,5795.39 J29.146@4411.14,5795.39
"HSEC_MII1_RXDV (14)": J29.142 J49.3 | length 291.4
  Top Layer w10: J49.3@4125,5745 4132.76,5737.24 4406.3,5737.24 J29.142@4411.14,5732.4
"HSEC_MII1_RXLINK (14)": J29.140 J49.2 | length 409.3
  Top Layer w10: J49.2@4025,5645 4080.91,5700.91 J29.140@4411.14,5700.91
"HSEC_MII1_TXD1 (13)": J29.150 J49.7 | length 322
  Top Layer w10: J49.7@4125,5945 4211.61,5858.39 J29.150@4411.14,5858.39
"HSEC_MII1_TXD3 (13)": J29.152 J49.8 | length 444.2
  Top Layer w10: J49.8@4025,5945 4067.48,5987.48 4161.31,5987.48 4258.9,5889.88 J29.152@4411.14,5889.88
"HSEC_MII1_TXEN (13)": J29.148 J49.6 | length 428.8
  Top Layer w10: J49.6@4025,5845 4032.56,5852.56 4072.48,5852.56 4107.4,5887.48 4161.31,5887.48 4221.9,5826.89 J29.148@4411.14,5826.89
I2C1_SCL: J19.8 J29.87 R158.1 R159.1 U27.6 | length 1662.7
  Top Layer w10: J29.87@4545,4084.06 4545.94,4085 4755,4085 4787.48,4052.52 4857.48,4052.52 J19.8@4915,3995 ; v1(5290,3945) 5285,3945 5290,3950 5475,3950 5505,3920 5505,3505.53 ; R158.1@5417.5,3609.49 U27.6@5417.5,3532.84 5417.5,3503.36 5423.36,3497.5 5499.14,3497.5 5505,3503.36
  Bottom Layer w10: J19.8@4915,3995 5020.32,3995 5027.13,3988.19 5027.13,3972.87 5050,3950 v1@5290,3950
I2C1_SDA: J19.7 J29.85 R157.1 R160.1 U27.5 | length 1460.7
  Top Layer w10: J29.85@4545,4052.56 4757.44,4052.56 J19.7@4815,3995 ; v1(5255,3975) 5255,3939 5270,3924 5356.36,3924 5357.36,3925 5472.57,3925 5490,3907.57 5490,3635.93 5467.5,3613.43 R157.1@5467.5,3609.49 U27.5@5467.5,3532.84
  Bottom Layer w10: J19.7@4815,3995 4824.07,4004.07 4849.07,4004.07 4897.52,4052.52 5017.83,4052.52 5020.32,4055 5030.32,4055 5050.32,4035 5051.92,4035 5066.92,4020 5210,4020 v1(5255,3975)
I2C2_SCL: J19.6 R217.2 R222.1 | length 619.9
  Top Layer w10: v1(5259,4005) 5274,3990 5385.52,3990 5391.38,3995.86 R217.2@5391.38,4072.76
  Bottom Layer w10: J19.6@4915,4095 4925,4105 5002.44,4105 5012.44,4115 5030.32,4115 5051.27,4094.05 5051.27,4093.02 5064.29,4080 5190,4080 5190,4074 v1(5259,4005)
I2C2_SDA: J19.5 R218.2 R223.1 | length 607.1
  Top Layer w10: v1(5270,4165) 5267.7,4162.7 5267.7,4143.03 5263.19,4138.51 5263.19,4097.13 5285,4075.32 R218.2@5285,4071.38
  Bottom Layer w10: J19.5@4815,4095 4822.56,4102.56 4847.56,4102.56 4898.1,4153.1 4902.24,4153.1 4903.02,4153.1 ccw(c4910,4195) 4924.3,4155 4992.44,4155 5012.44,4175 5016.38,4175 5030.32,4175 5052.13,4153.19 5254.94,4153.19 5266.75,4165 v1(5270,4165)
IGN_SW: D31.2 R132.1 SW1.2 | length 6711.3
  Top Layer w10: SW1.2@260.91,3535 260.91,3543.22 287.21,3569.51 295.43,3569.51 415.91,3690 610,3690 658.85,3738.85 2105.56,3738.85 2114.41,3730 3329.52,3730 3353.52,3706 3453,3706 v1(3455,3704) D31.2@3455,3663.31 ; R132.1@1889.99,2573.62 1889.99,2569.68 1865.15,2544.84 1865.15,2354.85 1990,2230 3335.36,2230 3562.35,2456.99 v1(3562.35,3612.65)
  Bottom Layer w10: v1(3455,3704) 3544.05,3614.95 3560.05,3614.95 v1(3562.35,3612.65)
IPROPI1: C69.1 J17.4 R99.2 R111.2 R184.2 | length 5251.9
  Top Layer w10: R99.2@744.41,4732.64 745.06,4731.99 745.06,4692.97 745.71,4692.32 C69.1@745.71,4660 ; C69.1@745.32,4660 C69.1@745.71,4660 ; v1@1205.41,4345 v1(1200.05,4345) 962.37,4345 858.09,4449.27 858.09,4621.91 845,4635 772.28,4635 747.28,4660 C69.1@745.71,4660 ; v1(1356.07,4344) 1358.37,4341.7 1358.37,4331.98 1362.07,4328.28 1362.07,3870.5 1463.73,3768.85 3766.15,3768.85 v1@3775,3760 ; v1(3780,3555) 3780,2760 3795,2745 3945,2745 3998.64,2798.64 R184.2@4141.38,2798.64
  Bottom Layer w10: v1(1200.05,4345) 1200.56,4344.5 1355.57,4344.5 v1(1356.07,4344) ; v1(3779.69,3766) 3780,3765.69 v1(3780,3555)
IPROPI2: C66.1 J17.6 R91.2 R93.2 R188.2 | length 5682.3
  Top Layer w10: R91.2@743.52,5152.01 743.52,5153.98 731.02,5166.48 731.02,5185 731.02,5215 732.28,5215 757.28,5240 850.36,5240 905,5185.36 905,4872.43 950,4827.43 950,4500.86 955.86,4495 v1(1200.05,4495) ; v1(1365.05,4495) 1452.07,4407.98 1452.07,3957.93 1608,3802 3794.6,3802 3795.31,3801.3 3803.79,3801.3 v1(3806.09,3799) ; v1@3810,3542.24 3810,2865 3830,2845 3945,2845 3952.56,2852.56 3992.48,2852.56 4035.83,2895.91 R188.2@4141.38,2895.91
  Bottom Layer w10: v1(1200.05,4495) v1(1365.05,4495) ; v1(3806.09,3799) 3808.04,3797.04 v1@3808.04,3544.2
  other v1: 3810,3550
IPROPI3: C70.1 J17.8 R101.2 R113.2 R192.2 | length 6167
  Top Layer w10: R101.2@787.5,5635.31 788.91,5633.91 788.91,5566.41 C70.1@790.32,5565 792.28,5565 797.13,5560.16 797.13,5532.87 820,5510 898.79,5510 1048.79,5660 1575.57,5660 1634,5601.57 1634,4082.21 1711.21,4005 3817.75,4005 3821.75,4009 v1(3825,4009) ; v1(3840,3555) 3840,2960 3855,2945 3945,2945 3952.56,2952.56 3992.48,2952.56 4033.11,2993.18 R192.2@4141.38,2993.18
  Bottom Layer w10: v1(3825,4009) 3825,4007.75 3839.8,3992.96 3839.8,3981.96 3840,3981.75 v1(3840,3555)
IPROPI4: C67.1 J17.10 R92.2 R94.2 R194.2 | length 6393.9
  Top Layer w10: R92.2@763.52,6077.01 763.52,6078.98 751.02,6091.48 R94.2@751.02,6117.32 749.06,6117.32 744.21,6122.17 744.21,6124.13 750.32,6118.03 C67.1@750.32,6150 752.28,6150 772.28,6170 870,6170 1004,6036 1004,5775.09 1014.09,5765 1619.06,5765 1755,5629.06 1755,4150 1800,4105 3847.93,4105 3853.93,4111 v1(3857.18,4111) ; 3870,3542.24 3870,3120 3945,3045 3952.56,3052.56 3992.48,3052.56 4030.38,3090.45 R194.2@4141.38,3090.45
  Bottom Layer w10: v1(3857.18,4111) 3859.48,4108.7 3859.48,4090.52 3870,4080 v1(3870,3555)
KL15_IN: R134.2 SW1.3 | length 109.9
  Top Layer w10: SW1.3@449.88,3535 454.88,3540 R134.2@557.76,3540
KL15_OK_B: D29.1 Q8.1 R123.1 | length 222.8
  Top Layer w10: R123.1@1974.99,2705 2034.99,2705 ; Q8.1@2032.59,2680.59 2032.59,2702.6 2034.99,2705 ; D29.1@2159.99,2675 2129.99,2705 2034.99,2705
KL15_OK_D: D29.2 Q9.3 R126.1 | length 156.9
  Top Layer w10: Q9.3@2174.99,2552.4 2178.89,2556.3 2178.89,2579.21 2194.67,2595 R126.1@2198.61,2595 2202.55,2595 2246.6,2639.06 D29.2@2246.6,2675
KL15_OK_E: Q8.2 R126.2 | length 133
  Top Layer w10: Q8.2@2032.59,2629.41 2113.02,2629.41 2147.43,2595 R126.2@2151.37,2595
KL15_OK_G: D30.1 J29.62 Q9.1 R128.1 | length 3881.7
  Top Layer w10: R128.1@1984.99,2470 2048.3,2470 D30.1@2069.99,2491.69 2100.52,2491.69 2114.61,2477.6 Q9.1@2149.4,2477.6 2149.4,2475.04 2189.44,2435 2189.44,2385.56 2325,2250 3329.14,2250 3520,2440.86 3520,3630 3590,3700 4110,3700 v1(4120,3710) ; v1(4321,3680) 4324.25,3680 4329.64,3674.61 J29.62@4411.14,3674.61
  Bottom Layer w10: v1(4120,3710) 4290,3710 4320,3680 v1(4321,3680)
KL15_OK_LED: D27.1 Q8.3 | length 142.1
  Top Layer w10: D27.1@1971.48,2640 1986.48,2655 Q8.3@2107.39,2655
KL30_OK_B: D28.1 Q7.1 R122.1 | length 212.8
  Top Layer w10: R122.1@2134.99,2825 2138.93,2825 2163.34,2800.59 Q7.1@2197.59,2800.59 2200.15,2800.59 2214.56,2815 D28.1@2331.69,2815
KL30_OK_E: Q7.2 R125.2 | length 129
  Top Layer w10: Q7.2@2197.59,2749.41 2197.88,2749.7 2326.07,2749.7 R125.2@2326.37,2750
KL30_OK_LED: D26.1 Q7.3 | length 150.7
  Top Layer w10: D26.1@2129.99,2755 2169.11,2755 2189.11,2775 Q7.3@2272.39,2775
LED_BQ_12V: D37.2 R146.2 | length 73.9
  Top Layer w20: R146.2@2629.99,3070 2629.99,3113.5 D37.2@2651.48,3135
LED_VCC3V3: D34.2 R144.2 | length 79.3
  Top Layer w10: R144.2@2227.43,3320 2249.99,3297.44 D34.2@2249.99,3250
LED_VCC5V: D39.2 R149.2 | length 56.3
  Top Layer w10: R149.2@1907.23,3470 D39.2@1963.49,3470
LS_EN1: J29.88 R96.1 | length 5257.9
  Top Layer w10: R96.1@711.02,5152.01 708.5,5154.53 708.5,5232.65 735.86,5260 851.57,5260 920,5191.57 920,4878.64 965,4833.64 965,4525.86 970.86,4520 v1(1183.81,4520) ; v1(1341,4530.34) 1341.66,4531 1359,4531 1467.07,4422.93 1467.07,3967.93 1615,3820 4057.43,3820 4130,3892.57 4130,4084.14 4135.86,4090 4386.66,4090 4387.77,4088.9 4406.3,4088.9 J29.88@4411.14,4084.06
  Bottom Layer w10: v1(1183.81,4520) 1327.41,4520 1337.75,4530.34 v1(1341,4530.34)
LS_EN2: J29.86 R102.1 | length 4777.8
  Top Layer w10: R102.1@707.2,4732.64 707.2,4662.31 749.52,4620 830,4620 843.09,4606.91 843.09,4436.91 960,4320 v1(1185.05,4320) v1@1186.96,4320 ; v1(1341.07,4319.58) 1341.07,3870.29 1457.51,3753.85 2769.48,3753.85 2778.33,3745 4090.3,3745 4160,3814.7 4160,4039.14 4165.86,4045 4389.81,4045 4397.36,4052.56 J29.86@4411.14,4052.56
  Bottom Layer w10: v1(1185.05,4320) 1185.27,4319.79 1340.86,4319.79 v1(1341.07,4319.58)
LS_EN3: J29.96 R97.1 | length 5729.8
  Top Layer w10: R97.1@731.02,6076.69 731.02,6101.53 720,6112.55 720,6155.48 749.52,6185 880,6185 1019,6046 1019,5785.86 1024.86,5780 1625.27,5780 1770,5635.27 1770,4156.21 1806.21,4120 3836.48,4120 3848.48,4132 3913.21,4132 3918.92,4137.7 3936.7,4137.7 v1(3939,4140) ; v1(4080.96,4209.12) 4081.84,4210 J29.96@4411.14,4210.04 J29.96@4411.14,4210.04
  Bottom Layer w10: v1(3939,4140) 3940,4141 3940,4195 3954.12,4209.12 v1(4080.96,4209.12)
LS_EN4: J29.100 Q6.3 R103.1 | length 8193.7
  Top Layer w10: R103.1@745,5635.31 745,5633.35 768.5,5609.84 768.5,5551.02 770,5549.52 770,5515 790,5495 905,5495 1055,5645 1569.36,5645 1619,5595.36 1619,4076 1707,3988 4042.14,3988 4055,4000.86 4055,4272.17 4055.86,4273.03 ; J29.100@4411.14,4273.03 4055.86,4273.03 ; v1@4699.85,4805 4696.07,4808.79 4131.21,4808.79 4055.86,4733.43 4055.86,4273.03 ; v1@5035,5326.14 5035,5326 5035.14,5326.14 5035.14,5850.1 5072.54,5887.5 Q6.3@5075.1,5887.5
  Bottom Layer w10: v1@4705.14,4806 4705.14,5221 v1(4745.14,5261) ; v1@4750,5270 4807.48,5327.48 5033.66,5327.48 v1(5035.14,5326)
  other v1: 4705,4800
LS_EN_COM: J29.102 U15.1 U15.2 U15.3 U15.4 U15.5 U15.6 U15.7 U15.8 U16.1 U16.2 U16.3 U16.4 U16.5 U16.6 U16.7 U16.8 | length 6344.7
  Top Layer w10: v4(1465,5801) 1625.49,5801 1785,5641.49 1785,4180 1830,4135 3830.27,4135 3842.27,4147 3907,4147 3940,4180 3940,4294 v1(3939,4295) ; v1(4076.86,4305) 4077.09,4304.76 4410.91,4304.76 J29.102@4411.14,4304.53
  Bottom Layer w10: U16.1@940,6538.07 U16.2@990,6538.07 U16.3@1040,6538.07 U16.4@1090,6538.07 U16.5@1140,6538.07 U16.6@1190,6538.07 U16.7@1240,6538.07 U16.8@1290,6538.07 1290,6455 1470,6275 1470,6042.12 1465,6037.12 v4(1465,5801) ; U15.8@1040,5700 U15.7@1090,5700 U15.6@1140,5700 U15.5@1190,5700 U15.4@1240,5700 U15.3@1290,5700 U15.2@1340,5700 ; U15.1@1390,5700 U15.2@1340,5700 ; v4@1470,5801 1468.25,5801 1462.7,5795.46 1462.7,5762.7 1420.95,5720.95 1390,5720.95 1346.81,5720.95 1340,5714.14 U15.2@1340,5700 ; v1(3939,4295) 3941.86,4295 3951.86,4305 v1(4076.86,4305)
LS_OUT1: C72.2 J22.1 U17.18 U17.19 U17.20
LS_OUT2: C71.2 J21.1 U17.9 U17.10 U17.11 | length 51.2
  Top Layer w10: U17.11@566.46,5056.5 592.05,5056.5 U17.9@617.64,5056.5
LS_OUT3: C74.2 J24.1 U18.18 U18.19 U18.20 | length 515.1
  Top Layer w50: J24.1@161,5722.8 184.66,5699.13 358.24,5699.13 377.47,5679.91 581.41,5679.91 600.12,5698.62 600.12,5734.91 604.65,5739.43 U18.19@612.45,5739.43
LS_OUT4: C73.2 J27.3 U18.9 U18.10 U18.11 | length 303.9
  Top Layer w10: C73.2@445,5972.56 445.98,5972.56 456.73,5983.31 456.73,6001.73 465,6010 609.77,6010
  Top Layer w80: J27.3@530,6195 609.77,6115.23
LS_OUT_COM: J14.1 J21.2 J22.2 J24.2 R90.2 U15.13 U15.14 U15.15 U15.16 U15.17 U15.18 U15.19 U15.20 U16.13 U16.14 U16.15 U16.16 U16.17 U16.18 U16.19 U16.20 | length 4225
  Top Layer w10: v1(1445,6120) 1445.16,6119.84 1489.84,6119.84 R90.2@1490,6119.69
  Top Layer w50: 60,5135 J21.2@165,5135 ; 60,5580 65,5585 J24.2@161,5585
  Top Layer w80: J22.2@161,4671.67 157.17,4675.49 101.86,4675.49 60,4717.36 60,5135 60,5580 60,5820 ; J14.1@330,6055 330,5866.86 283.14,5820 60,5820 ; 850,6255 850,6300 800,6350 539.29,6350 482.87,6293.58 98.15,6293.58 60,6255.43 60,5820
  Bottom Layer w10: U15.20@1390,6066.14 1390,6091.69 1396.81,6098.5 1423.5,6098.5 v1(1445,6120)
  Bottom Layer w50: U16.20@940,6171.93 U16.19@990,6171.93 U16.18@1040,6171.93 ; U15.13@1040,6066.14 U15.14@1090,6066.14 U15.15@1140,6066.14 U15.15@1144.61,6066.14 ; U16.13@1290,6171.93 U16.14@1240,6171.93 U16.15@1190,6171.93 U16.16@1140,6171.93 U16.17@1090,6171.93 U16.18@1040,6171.93 ; U15.20@1390,6066.14 U15.19@1340,6066.14 U15.18@1290,6066.14 U15.17@1240,6066.14 U15.16@1190,6066.14 U15.15@1144.61,6066.14 ; U16.18@1040,6171.93 1040,6170.75 1064.41,6146.34 U15.15@1144.61,6066.14
  other v1: 865,6230 833.5,6230.91 833.5,6265.91 863.5,6265.91 833.5,6300.91 863.5,6300.91
LS_OUT_COM_S: C68.1 J17.14 R90.1 R95.2 R229.2 | length 5363.6
  Top Layer w10: R95.2@1455.16,6044.53 1489.84,6044.53 C68.1@1490,6044.37 ; R90.1@1490,6080.31 C68.1@1490,6044.37 ; v1@3896.89,4173.11 3885.79,4162 3836.06,4162 3824.06,4150 1840,4150 1800,4190 1800,5648.56 1520,5928.56 1520,6012.4 1490,6042.4 C68.1@1490,6044.37 ; v1(3930,3555) 3930,3500 3902.52,3472.52 3902.52,3287.48 J17.14@3950,3240 ; J17.14@3955,3245 3999.18,3289.18 4114.01,3289.18 4116.49,3286.7 4139.68,3286.7 R229.2@4141.38,3285
  Bottom Layer w10: v1(3902.18,4178) 3902.18,4174.75 3915,4161.93 3915,3960.7 3930,3945.7 v1(3930,3555)
LSD_FAULT1: J29.125 J45.4 R85.2 R98.1 R106.2 U17.26 U19.12 | length 7710.6
  Top Layer w10: R85.2@770,4519.84 R106.2@770,4555 769.84,4555.16 769.84,4589.84 R98.1@769.68,4590 v1(805,4590) ; U17.26@771.18,4828.15 771.18,4749.48 875,4645.66 875,4453.58 958.58,4370 v1(1183.81,4370) ; v1@1348.8,4370 1351.1,4367.7 1362.06,4367.7 1377.07,4352.7 1377.07,3882.93 1473,3787 3788.39,3787 3797.39,3778 4097.14,3778 4145,3825.86 4145,4051.26 4159.74,4066 v1(4160,4066) ; v1(4170,4330) 4085,4330 4070.86,4344.14 4070.86,4720.86 4141.11,4791.11 4563.89,4791.11 4580,4775 4771.75,4775 4776.75,4780 v1(4780,4780) ; J29.125@4545,5480.43 4659.57,5480.43 4865,5275 4887.82,5275 4898.34,5264.48 4915.52,5264.48 4952.52,5227.48 5000.48,5227.48 5002.96,5225 v1(5140,5225) ; U19.12@5186.18,5449.53 5186.18,5400.03 5195,5391.21 v1(5195,5225)
  Bottom Layer w10: v1@805,4595 844.05,4634.05 844.05,4661.82 v1@845.53,4663.3 ; v1(1183.81,4370) v1@1348.8,4370 ; v1(4160,4066) 4160,4312.5 4167.7,4320.2 4167.7,4327.7 v1(4170,4330) ; v1(4780,4780) 4780,5190 J45.4@4865,5275 ; v1(5140,5225) v1(5195,5225)
  other v1: 1347.81,4372 850,4665
LSD_FAULT2: J29.121 J45.2 R86.2 R100.1 R108.2 U18.26 U19.13 | length 8254.4
  Top Layer w10: R100.1@735,5585 735.16,5585 740,5580.16 v1(740,5520) ; U18.26@791.18,5738.15 795.04,5734.29 795.04,5708.5 821.72,5681.81 825.16,5681.81 830,5676.97 R108.2@830,5675 830,5673.03 851.67,5651.36 851.67,5579.98 889.17,5542.48 v1@889.36,5542.3 ; v1(890,5534) 889.36,5534.64 v1@889.36,5542.3 ; J29.121@4545,5417.44 4618.78,5417.44 4861.22,5175 4875,5175 4907.48,5142.52 5142.52,5142.52 5220,5220 5220,5303.3 5218.19,5305.11 5218.19,5418.51 5211.77,5424.92 U19.13@5211.77,5449.53 ; v1(4830,4785) 4790,4825 4126.21,4825 4040,4738.79 4040,4043.96 4025.78,4029.75 3835.95,4029.75 3835.7,4030 1707.43,4030 1649,4088.43 1649,5607.78 1581.78,5675 1034.2,5675 902.99,5543.78 902.27,5543.78 900.78,5542.3 v1@889.36,5542.3
  Bottom Layer w10: v1(740,5520) 802.47,5520 809.47,5513 869,5513 v1(890,5534) ; v1(4830,4785) 4830,5140 J45.2@4865,5175
MCU_WAKE: J29.64 R147.1 | length 3909.5
  Top Layer w10: R147.1@2478.97,2940 R147.1@2472.59,2933.62 2505,2933.62 2505,2315 2545,2275 3330,2275 3498,2443 3498,3648 3565,3715 4090,3715 v1(4115,3740) ; v1(4321,3715) 4323.96,3715 4332.86,3706.1 J29.64@4411.14,3706.1
  Bottom Layer w10: v1(4115,3740) 4296,3740 v1(4321,3715)
NetBT1_2: BT1.2 U27.3 | length 2014
  Top Layer w10: BT1.2@5190,1635 5450,1635 5500,1685 5500,3243.39 5466.63,3276.76 5453.1,3276.76 5417.5,3312.36 U27.3@5417.5,3326.14
NetC3_1: C3.1 CO1.1 R3.1 R5.2 U1.3
NetC5_1: C5.1 J1.2 L1.4 R4.1 R8.2 R11.2 U3.2 | length 1026.6
  Top Layer w10: R4.1@1239.17,1126.38 1239.17,1122.44 1232.36,1115.63 1201.88,1115.63 1189.17,1102.91 L1.4@1189.17,1095.87 1221.88,1095.87 1253.87,1063.88 1253.87,1061.99 1298.93,1016.93 1463.58,1016.93 1484.17,996.34 R11.2@1484.17,955 1484.17,913.66 1504.76,893.07 1539.6,893.07 1561.25,871.42 R8.2@1561.25,820 1561.25,809.17 1520.35,768.27 1520.35,748.7 1506.65,735 C5.1@1505.66,735 1505.66,705.28 1456.43,656.04 1404.17,603.78 U3.2@1404.17,590 1404.17,551.86 J1.2@1445,511.02
NetC6_2: C6.2 R8.1 R13.2 | length 164.1
  Top Layer w10: R13.2@1294.17,820 1355.66,820 C6.2@1369.17,806.5 1382.67,820 R8.1@1447.08,820
NetC7_2: C7.2 J1.3 L1.3 R11.1 R13.1 R14.1 U3.1 | length 897
  Top Layer w10: R14.1@1042.57,1138.72 1042.57,1134.78 1049.38,1127.97 1058.64,1127.97 1069.17,1117.44 1078.03,1117.44 1090.74,1104.72 L1.3@1090.74,1095.87 1090.74,1054.29 1135.74,1009.29 1231.29,1009.29 1251.88,988.7 R11.1@1251.88,955 1251.88,913.66 1231.29,893.07 1201.65,893.07 1179.99,871.42 R13.1@1179.99,820 1179.99,809.17 1221.49,767.68 1221.49,748.7 1235.19,735 C7.2@1236.18,735 1236.18,696.97 1329.37,603.78 U3.1@1329.37,590 1336.18,583.19 1336.18,519.85 J1.3@1345,511.02
NetC10_1: C10.1 CO3.1 R15.1 R17.2 U4.3 | length 193.4
  Top Layer w10: CO3.1@2542.25,1848.8 2542.25,1775.16 U4.3@2546.67,1770.75 ; C10.1@2549.17,1956.89 CO3.1@2549.17,1861.89 CO3.1@2562.25,1848.8
NetC12_1: C12.1 J2.2 L2.4 R18.1 R22.2 R24.2 U6.2 | length 1047.3
  Top Layer w10: R18.1@2159.17,1122.24 2116.1,1122.24 2103.38,1109.53 L2.4@2103.38,1106.73 2103.38,1041.72 2109.24,1035.87 2307.67,1035.87 2330.74,1012.8 2359.72,1012.8 2380.31,992.2 R24.2@2380.31,950.87 2380.31,909.53 2432.55,857.28 2447.75,857.28 2468.34,836.69 R22.2@2468.34,825.87 2468.34,815.04 2420.35,767.05 2420.35,754.57 2406.65,740.87 C12.1@2405.66,740.87 2405.66,692.4 2306.57,593.31 U6.2@2306.57,579.53 2306.57,539.3 2312.52,539.3 2340.79,511.02 J2.2@2350,511.02
NetC13_2: C13.2 R22.1 R26.2 | length 184.5
  Top Layer w10: R26.2@2185,825.87 2203.5,807.36 C13.2@2269.17,807.36 2335.66,807.36 R22.1@2354.17,825.87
